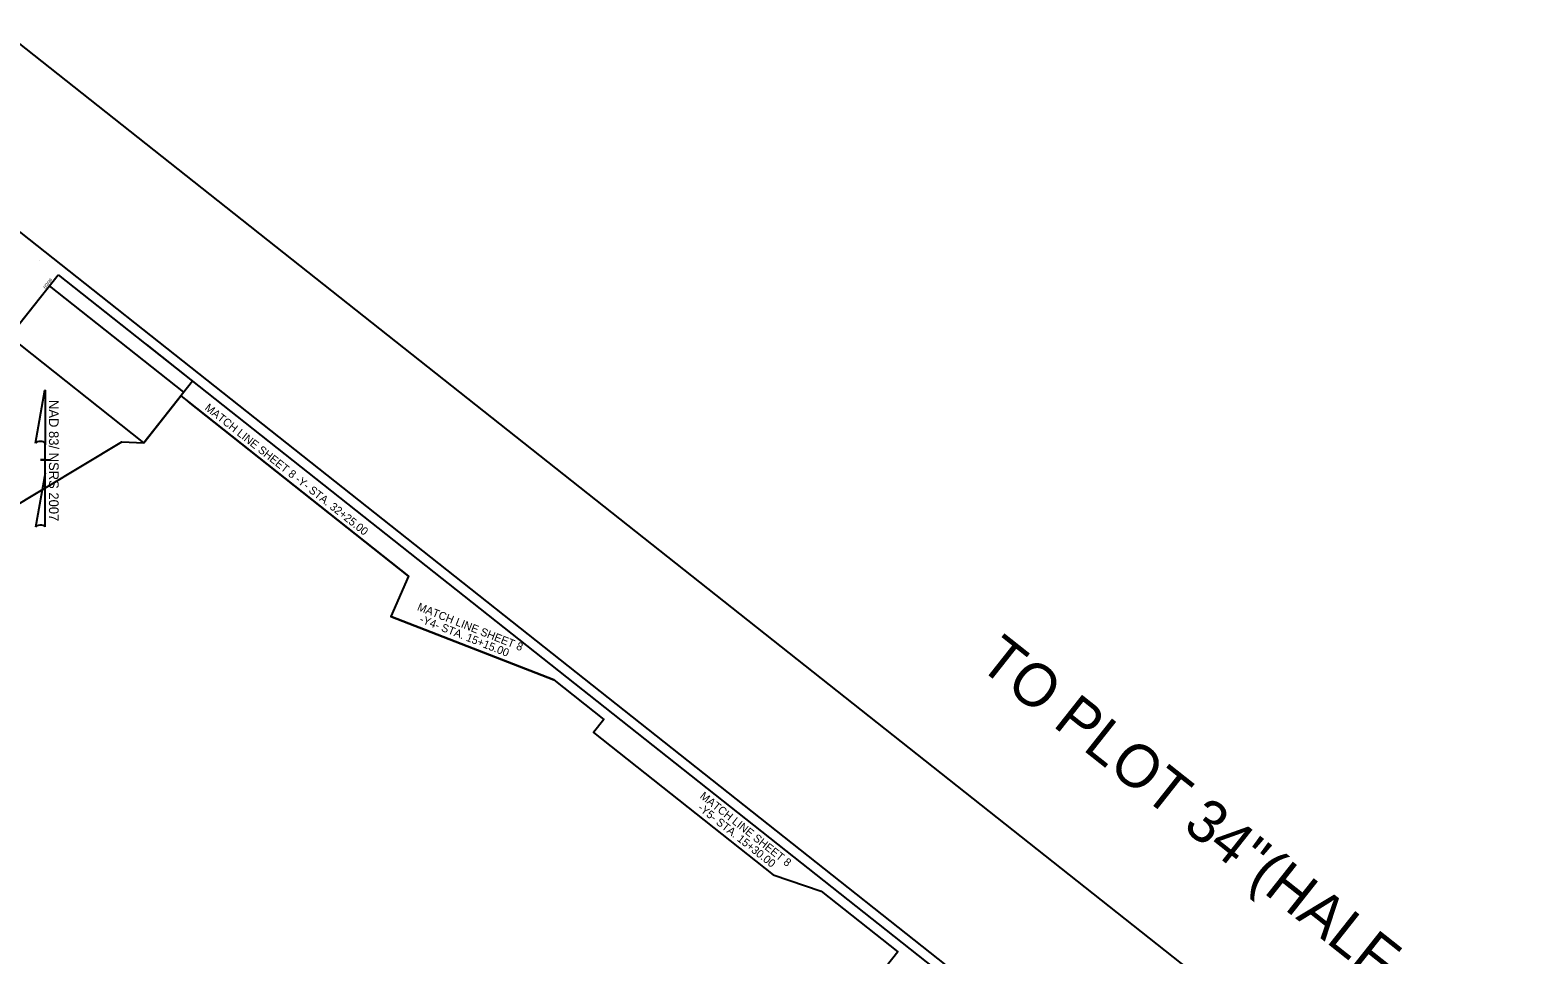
# Model space of a CAD drawing. Extents: x 1771636 to 1784627, y 798645 to 819978.
# Drawn here: x 1781866 to 1784477, y 813181 to 814799 of the extents above; entities that cross this region are included whole.
import ezdxf

# ---------------------------------------------------------------- set-up
doc = ezdxf.new("R2010")
doc.units = 0
for name, color, linetype in [('Exist Hydro Stream Flow Arrow CELL', 7, 'Continuous'), ('Exist Other Culture Fence Line', 7, 'Continuous'), ('Exist Other Culture Gate', 7, 'Continuous'), ('Exist Other Culture Well CELL', 7, 'Continuous'), ('Exist Utilities Other Located Object CELL', 7, 'Continuous'), ('Exist Utilities Power Joint Use Telephone CELL', 7, 'Continuous'), ('Exist Utilities Telephone Pole CELL', 7, 'Continuous')]:
    doc.layers.add(name, color=color, linetype=linetype)

msp = doc.modelspace()

# ---------------------------------------------------------------- linework, layer by layer
at = {"layer": 'Exist Hydro Stream Flow Arrow CELL'}
msp.add_lwpolyline([(1784297.9, 812505.9), (1781710.6, 814554.3), (1780665.3, 813234), (1783252.6, 811185.6)], close=True, dxfattribs=at)
at = {"layer": 'Exist Other Culture Gate'}
for p, q in [((1781876.2, 814075.6), (1781892.6, 814168.3)), ((1781892.7, 814168.3), (1781892.6, 814168.3)), ((1781892.7, 814168.3), (1781892.6, 814168.3)), ((1781892.7, 814168.3), (1781892.7, 814072.7)), ((1781892.7, 814023.1), (1781892.7, 814075.5)), ((1781892.7, 814072.7), (1781892.7, 814075.4)), ((1781884.7, 814046.3), (1781884.6, 814046.3)), ((1781891.8, 814046.3), (1781884.7, 814046.3)), ((1781884.8, 814046.3), (1781900.8, 814046.3)), ((1781892.7, 814023.1), (1781876, 813928.6)), ((1781892.8, 813929), (1781892.7, 814023.1))]:
    msp.add_line(p, q, dxfattribs=at)
for centre, start_param, end_param in [((1781884.5, 814074.6), 0.216388, 2.908219), ((1781884.5, 813928.2), 0.201328, 3.141593)]:
    msp.add_ellipse(centre, major_axis=(8.46, -0.06), ratio=0.461098, start_param=start_param, end_param=end_param, dxfattribs=at)
at = {"layer": 'Exist Other Culture Well CELL'}
msp.add_lwpolyline([(1784458, 812708.2), (1781817.4, 814798.8), (1780451.8, 813073.9), (1783092.4, 810983.3)], close=True, dxfattribs=at)
at = {"layer": 'Exist Utilities Other Located Object CELL'}
for p, q in [((1782466.7, 813891.9), (1782143.5, 814147.8)), ((1782528.7, 813842.8), (1782162.8, 814132.5)), ((1782528.7, 813842.8), (1782497.5, 813772.1)), ((1782783.1, 813661.2), (1782497.5, 813772.1)), ((1782783.1, 813661.2), (1782870.1, 813592.2)), ((1782870.1, 813592.2), (1782852, 813569.4)), ((1782852, 813569.4), (1783166.6, 813320.4)), ((1783166.6, 813320.4), (1783250.7, 813291.6)), ((1783250.7, 813291.6), (1783384.7, 813185.4))]:
    msp.add_line(p, q, dxfattribs=at)
at = {"layer": 'Exist Utilities Power Joint Use Telephone CELL'}
for p, q in [((1781883.7, 814395.5), (1781883.7, 814395.5)), ((1781900.1, 814350.7), (1782134.8, 814164.9)), ((1781984.7, 814284.1), (1781984.7, 814284.1)), ((1782038.6, 814272.9), (1782038.6, 814272.9)), ((1782070.5, 814247.7), (1782147.8, 814186.2))]:
    msp.add_line(p, q, dxfattribs=at)
for points in [[(1781915.6, 814370.3), (1784267.7, 812508.1), (1783243.5, 811214.5), (1780891.4, 813076.6)], [(1781915.6, 814370.3), (1782150.8, 814184.1), (1782065.5, 814076.3), (1781830.3, 814262.5)]]:
    msp.add_lwpolyline(points, close=True, dxfattribs=at)
at = {"layer": 'Exist Utilities Telephone Pole CELL'}
msp.add_lwpolyline([(1781415.8, 813710.5), (1782027.2, 814077.9), (1782065.5, 814076.3), (1782130.3, 814158.1), (1782143.5, 814147.8), (1782528.7, 813842.8), (1782497.5, 813772.1), (1782783.1, 813661.2), (1782870.1, 813592.2), (1782852, 813569.4), (1783166.6, 813320.4), (1783250.7, 813291.6), (1783384.7, 813185.4), (1782922.7, 812601.8)], dxfattribs=at)

# ---------------------------------------------------------------- texts
at = {"layer": 'Exist Other Culture Fence Line'}
for s, rotation, p in [('MATCH LINE SHEET 8 -Y- STA. 32+25.00', 321.6215, (1782170.9, 814135)), ('MATCH LINE SHEET 8 ', 338.4136, (1782542.7, 813783.8)), ('-Y4- STA. 15+15.00', 338.4136, (1782546.8, 813762.4)), ('MATCH LINE SHEET 8 ', 321.6309, (1783037.2, 813455.7)), ('-Y5- STA. 15+30.00', 321.6309, (1783033.7, 813435.1))]:
    msp.add_text(s, height=14, rotation=rotation, dxfattribs=at).set_placement(p)
at = {"layer": 'Exist Other Culture Gate'}
msp.add_text('NAD 83/ NSRS 2007', height=17, rotation=270, dxfattribs=at).set_placement((1781899.5, 814151.1))
at = {"layer": 'Exist Utilities Power Joint Use Telephone CELL'}
for s, height, rotation, p in [('6/2/99', 5.25, 51.6309, (1781893.2, 814345.4)), ('TO PLOT 34"(HALF SIZE)', 75, 321.6309, (1783522.9, 813685.3))]:
    msp.add_text(s, height=height, rotation=rotation, dxfattribs=at).set_placement(p)

doc.saveas('drawing.dxf')
